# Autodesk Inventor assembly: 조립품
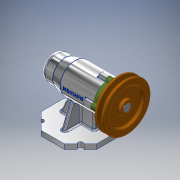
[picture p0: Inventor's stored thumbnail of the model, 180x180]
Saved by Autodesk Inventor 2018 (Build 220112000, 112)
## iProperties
Created: 2019-12
Part Number: 조립품
Material: 일반
Document SubType Name: Assembly
Designer: USER
Author: USER
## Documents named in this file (12)
- C:\Users\USER\Desktop\491204V1014\조립품.iam
- C:\Users\USER\Desktop\491204V1014\본체.ipt
- C:\Users\USER\Desktop\491204V1014\볼트 M4.ipt
- C:\Users\USER\Desktop\491204V1014\어댑터슬리브.ipt
- C:\Users\USER\Desktop\491204V1014\오일 실.ipt
- C:\Users\USER\Desktop\491204V1014\축.ipt
- C:\Users\USER\Desktop\491204V1014\커버.ipt
- C:\Users\USER\Desktop\491204V1014\키 5 x 5 x 16.ipt
- C:\Users\USER\Desktop\491204V1014\V벨트풀리.ipt
- C:\Users\USER\Desktop\491204V1014\멈춤나사 M3.ipt
- C:\Users\USER\Desktop\491204V1014\베어링 6004.ipt
- C:\Users\USER\Desktop\491204V1014\베어링 51202.ipt
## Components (1 placed, 1 different names)
1. V벨트풀리:2
